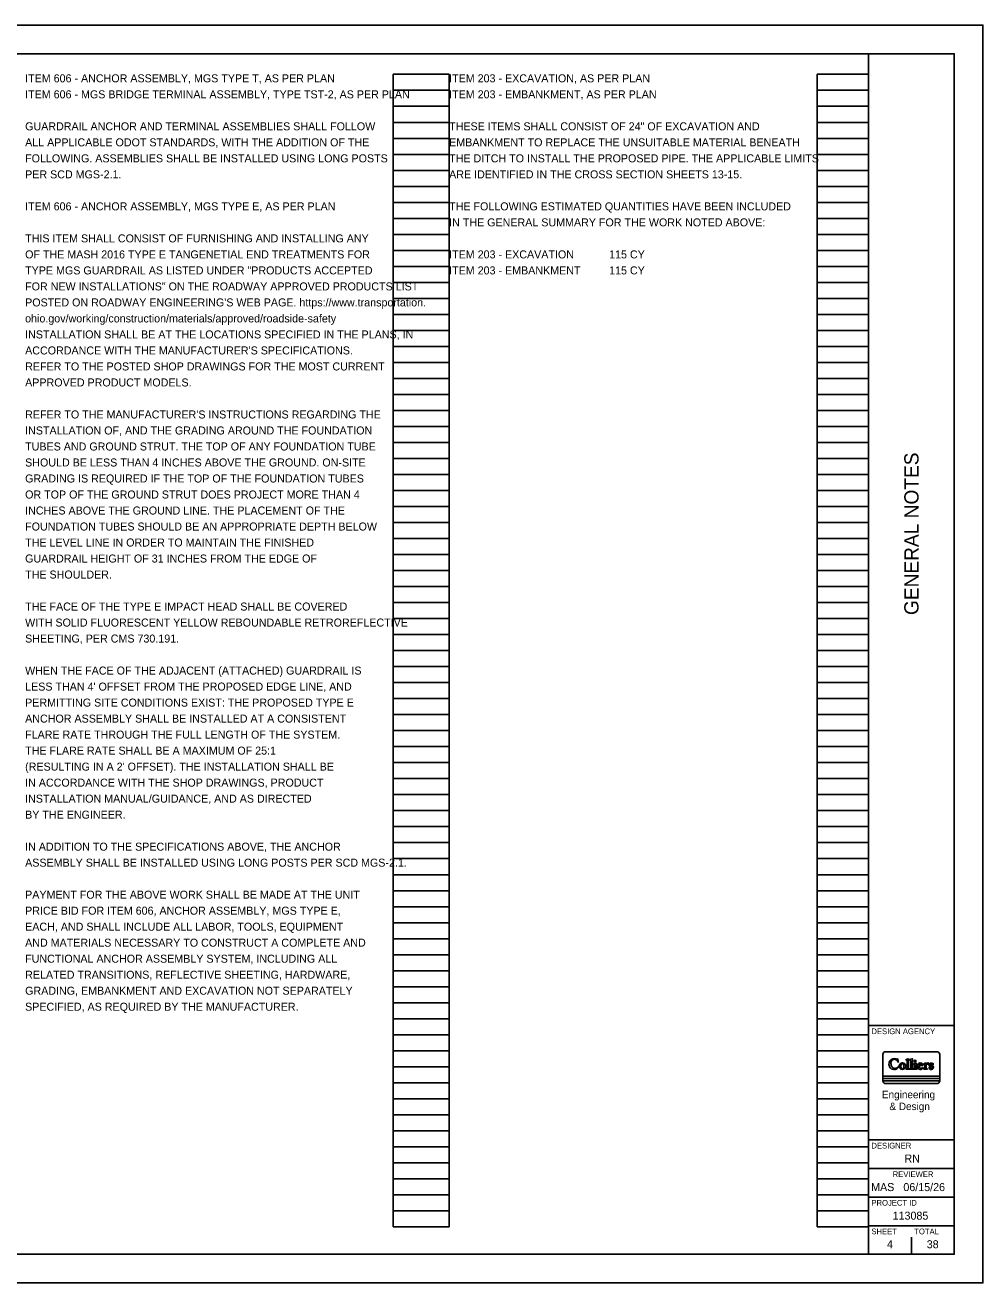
# Model space of a CAD drawing. Extents: x -24.6 to 58.4, y 0 to 22.8.
# Drawn here: x 17.24 to 34, y 0 to 22 of the extents above; entities that cross this region are included whole.
import ezdxf

# ---------------------------------------------------------------- set-up
doc = ezdxf.new("R2010")
doc.units = 0
for name, color, linetype in [('SH_Border', 7, 'Continuous'), ('SH_Cut_Line', 7, 'Continuous'), ('SH_Data', 7, 'Continuous'), ('SH_Text', 7, 'Continuous')]:
    doc.layers.add(name, color=color, linetype=linetype)

msp = doc.modelspace()

# ---------------------------------------------------------------- linework, layer by layer
at = {"layer": 'SH_Border'}
for p, q in [((32, 0.5), (32, 21.5)), ((32, 4.5), (33.5, 4.5)), ((32, 2.5), (33.5, 2.5)), ((32, 2), (33.5, 2)), ((32, 1.5), (33.5, 1.5)), ((32, 1), (33.5, 1))]:
    msp.add_line(p, q, dxfattribs=at)
msp.add_lwpolyline([(1.5, 21.5), (33.5, 21.5), (33.5, 0.5), (1.5, 0.5)], close=True, dxfattribs=at)
at = {"layer": 'SH_Cut_Line'}
msp.add_lwpolyline([(0, 0), (34, 0), (34, 22), (0, 22)], close=True, dxfattribs=at)
at = {"layer": 'SH_Data'}
for p, q in [((23.68, 0.98), (23.68, 21.14)), ((23.68, 21.14), (24.66, 21.14)), ((24.66, 0.98), (24.66, 21.14)), ((31.1, 0.98), (31.1, 21.14)), ((31.1, 21.14), (32, 21.14)), ((32, 0.98), (32, 21.14)), ((23.68, 20.86), (24.66, 20.86)), ((31.1, 20.86), (32, 20.86)), ((23.68, 20.58), (24.66, 20.58)), ((31.1, 20.58), (32, 20.58)), ((23.68, 20.3), (24.66, 20.3)), ((31.1, 20.3), (32, 20.3)), ((23.68, 20.02), (24.66, 20.02)), ((31.1, 20.02), (32, 20.02)), ((23.68, 19.74), (24.66, 19.74)), ((31.1, 19.74), (32, 19.74)), ((23.68, 19.46), (24.66, 19.46)), ((31.1, 19.46), (32, 19.46)), ((23.68, 19.18), (24.66, 19.18)), ((31.1, 19.18), (32, 19.18)), ((23.68, 18.9), (24.66, 18.9)), ((31.1, 18.9), (32, 18.9)), ((23.68, 18.62), (24.66, 18.62)), ((31.1, 18.62), (32, 18.62)), ((23.68, 18.34), (24.66, 18.34)), ((31.1, 18.34), (32, 18.34)), ((23.68, 18.06), (24.66, 18.06)), ((31.1, 18.06), (32, 18.06)), ((23.68, 17.78), (24.66, 17.78)), ((31.1, 17.78), (32, 17.78)), ((23.68, 17.5), (24.66, 17.5)), ((31.1, 17.5), (32, 17.5)), ((23.68, 17.22), (24.66, 17.22)), ((31.1, 17.22), (32, 17.22)), ((23.68, 16.94), (24.66, 16.94)), ((31.1, 16.94), (32, 16.94)), ((23.68, 16.66), (24.66, 16.66)), ((31.1, 16.66), (32, 16.66)), ((23.68, 16.38), (24.66, 16.38)), ((31.1, 16.38), (32, 16.38)), ((23.68, 16.1), (24.66, 16.1)), ((31.1, 16.1), (32, 16.1)), ((23.68, 15.82), (24.66, 15.82)), ((31.1, 15.82), (32, 15.82)), ((23.68, 15.54), (24.66, 15.54)), ((31.1, 15.54), (32, 15.54)), ((23.68, 15.26), (24.66, 15.26)), ((31.1, 15.26), (32, 15.26)), ((23.68, 14.98), (24.66, 14.98)), ((31.1, 14.98), (32, 14.98)), ((23.68, 14.7), (24.66, 14.7)), ((31.1, 14.7), (32, 14.7)), ((23.68, 14.42), (24.66, 14.42)), ((31.1, 14.42), (32, 14.42)), ((23.68, 14.14), (24.66, 14.14)), ((31.1, 14.14), (32, 14.14)), ((23.68, 13.86), (24.66, 13.86)), ((31.1, 13.86), (32, 13.86)), ((23.68, 13.58), (24.66, 13.58)), ((31.1, 13.58), (32, 13.58)), ((23.68, 13.3), (24.66, 13.3)), ((31.1, 13.3), (32, 13.3)), ((23.68, 13.02), (24.66, 13.02)), ((31.1, 13.02), (32, 13.02)), ((23.68, 12.74), (24.66, 12.74)), ((31.1, 12.74), (32, 12.74)), ((23.68, 12.46), (24.66, 12.46)), ((31.1, 12.46), (32, 12.46)), ((23.68, 12.18), (24.66, 12.18)), ((31.1, 12.18), (32, 12.18)), ((23.68, 11.9), (24.66, 11.9)), ((31.1, 11.9), (32, 11.9)), ((23.68, 11.62), (24.66, 11.62)), ((31.1, 11.62), (32, 11.62)), ((23.68, 11.34), (24.66, 11.34)), ((31.1, 11.34), (32, 11.34)), ((23.68, 11.06), (24.66, 11.06)), ((31.1, 11.06), (32, 11.06)), ((23.68, 10.78), (24.66, 10.78)), ((31.1, 10.78), (32, 10.78)), ((23.68, 10.5), (24.66, 10.5)), ((31.1, 10.5), (32, 10.5)), ((23.68, 10.22), (24.66, 10.22)), ((31.1, 10.22), (32, 10.22)), ((23.68, 9.94), (24.66, 9.94)), ((31.1, 9.94), (32, 9.94)), ((23.68, 9.66), (24.66, 9.66)), ((31.1, 9.66), (32, 9.66)), ((23.68, 9.38), (24.66, 9.38)), ((31.1, 9.38), (32, 9.38)), ((23.68, 9.1), (24.66, 9.1)), ((31.1, 9.1), (32, 9.1)), ((23.68, 8.82), (24.66, 8.82)), ((31.1, 8.82), (32, 8.82)), ((23.68, 8.54), (24.66, 8.54)), ((31.1, 8.54), (32, 8.54)), ((23.68, 8.26), (24.66, 8.26)), ((31.1, 8.26), (32, 8.26)), ((23.68, 7.98), (24.66, 7.98)), ((31.1, 7.98), (32, 7.98)), ((23.68, 7.7), (24.66, 7.7)), ((31.1, 7.7), (32, 7.7)), ((23.68, 7.42), (24.66, 7.42)), ((31.1, 7.42), (32, 7.42)), ((23.68, 7.14), (24.66, 7.14)), ((31.1, 7.14), (32, 7.14)), ((23.68, 6.86), (24.66, 6.86)), ((31.1, 6.86), (32, 6.86)), ((23.68, 6.58), (24.66, 6.58)), ((31.1, 6.58), (32, 6.58)), ((23.68, 6.3), (24.66, 6.3)), ((31.1, 6.3), (32, 6.3)), ((23.68, 6.02), (24.66, 6.02)), ((31.1, 6.02), (32, 6.02)), ((23.68, 5.74), (24.66, 5.74)), ((31.1, 5.74), (32, 5.74)), ((23.68, 5.46), (24.66, 5.46)), ((31.1, 5.46), (32, 5.46)), ((23.68, 5.18), (24.66, 5.18)), ((31.1, 5.18), (32, 5.18)), ((23.68, 4.9), (24.66, 4.9)), ((31.1, 4.9), (32, 4.9)), ((23.68, 4.62), (24.66, 4.62)), ((31.1, 4.62), (32, 4.62)), ((23.68, 4.34), (24.66, 4.34)), ((31.1, 4.34), (32, 4.34)), ((23.68, 4.06), (24.66, 4.06)), ((31.1, 4.06), (32, 4.06)), ((33.195, 4.043), (32.299, 4.043)), ((23.68, 3.78), (24.66, 3.78)), ((31.1, 3.78), (32, 3.78)), ((32.506, 3.913), (32.507, 3.91)), ((32.511, 3.864), (32.513, 3.859)), ((32.518, 3.765), (32.522, 3.77)), ((32.596, 3.846), (32.59, 3.846)), ((32.667, 3.745), (32.658, 3.745)), ((32.674, 3.881), (32.674, 3.753)), ((32.701, 3.752), (32.701, 3.916)), ((32.734, 3.745), (32.707, 3.745)), ((32.741, 3.879), (32.741, 3.751)), ((32.768, 3.751), (32.768, 3.916)), ((32.799, 3.745), (32.774, 3.745)), ((32.827, 3.846), (32.791, 3.832)), ((32.805, 3.812), (32.805, 3.751)), ((32.832, 3.749), (32.832, 3.843)), ((32.845, 3.745), (32.836, 3.745)), ((32.886, 3.802), (32.947, 3.802)), ((32.919, 3.81), (32.887, 3.81)), ((32.975, 3.745), (32.968, 3.745)), ((33, 3.846), (32.969, 3.831)), ((32.969, 3.825), (32.976, 3.821)), ((32.982, 3.81), (32.982, 3.753)), ((33.007, 3.828), (33.006, 3.843)), ((33.01, 3.753), (33.01, 3.807)), ((33.026, 3.745), (33.017, 3.745)), ((33.11, 3.833), (33.125, 3.816)), ((33.132, 3.82), (33.13, 3.835)), ((32.249, 3.533), (33.244, 3.533)), ((33.244, 3.533), (32.249, 3.533)), ((32.658, 3.737), (32.845, 3.737)), ((32.968, 3.737), (33.026, 3.737)), ((33.245, 3.535), (33.245, 3.575)), ((23.68, 3.5), (24.66, 3.5)), ((31.1, 3.5), (32, 3.5)), ((32.299, 3.485), (33.195, 3.485)), ((32.75, 3.5), (32.75, 3.5)), ((23.68, 3.22), (24.66, 3.22)), ((31.1, 3.22), (32, 3.22)), ((23.68, 2.94), (24.66, 2.94)), ((31.1, 2.94), (32, 2.94)), ((23.68, 2.66), (24.66, 2.66)), ((31.1, 2.66), (32, 2.66)), ((23.68, 2.38), (24.66, 2.38)), ((31.1, 2.38), (32, 2.38)), ((23.68, 2.1), (24.66, 2.1)), ((31.1, 2.1), (32, 2.1)), ((23.68, 1.82), (24.66, 1.82)), ((31.1, 1.82), (32, 1.82)), ((23.68, 1.54), (24.66, 1.54)), ((31.1, 1.54), (32, 1.54)), ((23.68, 1.26), (24.66, 1.26)), ((31.1, 1.26), (32, 1.26)), ((23.68, 0.98), (24.66, 0.98)), ((31.1, 0.98), (32, 0.98)), ((32.375, 0.675), (32.375, 0.675)), ((32.75, 0.5), (32.75, 0.8))]:
    msp.add_line(p, q, dxfattribs=at)
for points in [[(32.249, 3.993), (32.249, 3.617), (33.245, 3.617), (33.245, 3.993)], [(32.521, 3.861), (32.516, 3.886), (32.514, 3.914)], [(33.245, 3.575), (32.249, 3.575), (32.249, 3.535)]]:
    msp.add_lwpolyline(points, dxfattribs=at)
msp.add_lwpolyline([(33.245, 3.617), (32.249, 3.617), (32.249, 3.575), (33.245, 3.575)], close=True, dxfattribs=at)
msp.add_circle((32.815, 3.879), 0.0155, dxfattribs=at)
for centre, radius, start, end in [((32.299, 3.993), 0.0498, 90, 180), ((33.195, 3.993), 0.0498, 0, 90), ((32.456, 3.826), 0.0996, 122.7772, 219.4331), ((32.445, 3.817), 0.0857, 219.4331, 285.3506), ((32.526, 3.843), 0.135, 175.9543, 206.5569), ((32.457, 3.848), 0.0652, 110.6135, 175.9543), ((32.45, 3.835), 0.0884, 54.7696, 122.7772), ((32.458, 3.81), 0.059, 206.5569, 271.2175), ((32.45, 3.867), 0.0454, 67.8997, 110.6135), ((32.458, 3.828), 0.0773, 271.2175, 317.7042), ((32.437, 3.835), 0.0794, 21.2674, 67.8997), ((32.44, 3.834), 0.104, 285.3506, 318.3029), ((32.503, 3.91), 0.00381, 234.7696, 0.2433), ((32.51, 3.914), 0.00392, 10.93, 183.8175), ((32.516, 3.862), 0.00427, 213.048, 354.7379), ((32.518, 3.773), 0.00456, 317.5815, 137.7042), ((32.594, 3.79), 0.0573, 155.0154, 195.9836), ((32.593, 3.79), 0.0568, 195.9836, 247.4134), ((32.591, 3.791), 0.0549, 91.4708, 155.0154), ((32.627, 3.79), 0.0628, 159.8672, 197.1421), ((32.617, 3.787), 0.0527, 197.1421, 229.9048), ((32.613, 3.795), 0.0485, 128.4847, 159.8672), ((32.592, 3.822), 0.0143, 51.5153, 128.4847), ((32.593, 3.759), 0.0157, 229.9048, 310.0952), ((32.596, 3.791), 0.0547, 22.5432, 90), ((32.572, 3.797), 0.0457, 8.6045, 51.5153), ((32.573, 3.782), 0.0463, 311.5123, 356.3189), ((32.586, 3.797), 0.0652, 292.5866, 340.2533), ((32.532, 3.787), 0.0872, 354.2931, 11.1311), ((32.599, 3.792), 0.0508, 340.2533, 22.5432), ((32.657, 3.901), 0.00323, 122.5943, 271.3615), ((32.658, 3.741), 0.00412, 90, 270), ((32.544, 4.221), 0.336, 289.2258, 296.5694), ((32.657, 3.881), 0.0166, 0, 91.3615), ((32.667, 3.752), 0.00695, 270, 7.6881), ((32.696, 3.916), 0.00466, 0.7043, 112.8976), ((32.709, 3.752), 0.00806, 180, 256.9766), ((32.724, 3.902), 0.00377, 108.5217, 257.147), ((32.641, 4.168), 0.275, 287.2899, 295.7863), ((32.722, 3.879), 0.019, 0, 85.065), ((32.734, 3.751), 0.0065, 270, 3.1556), ((32.763, 3.916), 0.00504, 3.9002, 114.2106), ((32.775, 3.751), 0.00652, 179.2506, 264.6402), ((32.794, 3.829), 0.00399, 126.9098, 263.7558), ((32.792, 3.812), 0.0128, 0, 83.7558), ((32.799, 3.75), 0.00532, 270, 12.3402), ((32.829, 3.843), 0.00324, 356.2318, 111.3032), ((32.837, 3.749), 0.00485, 180, 266.7746), ((32.845, 3.741), 0.00381, 270, 90), ((32.936, 3.789), 0.0786, 158.9201, 196.7689), ((32.904, 3.78), 0.0455, 196.7689, 259.4625), ((32.906, 3.801), 0.0468, 107.3884, 158.9201), ((32.928, 3.794), 0.0459, 174.8749, 230.9242), ((32.886, 3.798), 0.00367, 90, 174.8749), ((32.917, 3.807), 0.0332, 120.4846, 167.2691), ((32.887, 3.813), 0.00338, 167.2691, 270), ((32.909, 3.792), 0.0557, 72.6116, 107.3884), ((32.906, 3.79), 0.0563, 259.4625, 329.9587), ((32.92, 3.784), 0.0321, 230.9242, 328.1623), ((32.907, 3.823), 0.0144, 42.3189, 120.4846), ((32.901, 3.817), 0.0231, 354.1231, 42.3189), ((32.918, 3.815), 0.00543, 277.2594, 354.1231), ((32.914, 3.809), 0.0381, 357.2625, 72.6116), ((32.946, 3.807), 0.00555, 272.7564, 357.2625), ((32.951, 3.764), 0.00454, 329.9587, 148.1623), ((32.968, 3.741), 0.00381, 91.0116, 270), ((32.971, 3.828), 0.0034, 121.2415, 241.2505), ((32.975, 3.752), 0.00704, 270, 9.7141), ((32.969, 3.81), 0.0136, 0, 59.7444), ((33.002, 3.843), 0.00375, 6.4513, 116.174), ((33.009, 3.828), 0.00158, 185.3907, 323.4477), ((33.094, 3.765), 0.104, 130.2856, 143.4477), ((33.033, 3.807), 0.0235, 141.4263, 180.0327), ((33.018, 3.752), 0.00796, 179.3196, 263.9925), ((33.023, 3.815), 0.0105, 58.8554, 141.4263), ((33.038, 3.831), 0.0179, 49.7144, 130.2856), ((33.026, 3.741), 0.00381, 270, 90), ((33.038, 3.839), 0.018, 238.8554, 310.2856), ((33.041, 3.835), 0.0124, 310.2856, 49.7144), ((33.093, 3.812), 0.0332, 143.4089, 199.3264), ((33.065, 3.768), 0.00485, 20.4198, 193.2731), ((32.948, 3.74), 0.116, 4.8826, 13.2731), ((33.087, 3.81), 0.0263, 199.3264, 242.7351), ((33.077, 3.751), 0.014, 184.8826, 242.2064), ((33.093, 3.812), 0.0334, 105.6066, 143.4089), ((33.118, 3.787), 0.0516, 200.4198, 231.7135), ((33.093, 3.782), 0.0486, 242.2064, 319.0024), ((33.141, 3.915), 0.144, 242.7351, 255.1442), ((33.093, 3.822), 0.0133, 123.6114, 236.3886), ((33.099, 3.79), 0.0558, 61.5074, 105.6066), ((33.099, 3.813), 0.0238, 78.1441, 123.6114), ((33.111, 3.85), 0.0468, 236.3886, 262.0524), ((33.098, 3.761), 0.0185, 231.7135, 325.4966), ((33.101, 3.825), 0.0115, 42.5173, 78.1441), ((33.1, 3.76), 0.016, 325.4966, 75.1442), ((33.099, 3.763), 0.0407, 40.9976, 82.0524), ((33.128, 3.819), 0.00433, 219.7222, 9.1323), ((33.122, 3.833), 0.00795, 16.8946, 61.5074), ((33.107, 3.77), 0.0305, 319.0024, 40.9976), ((32.299, 3.535), 0.0498, 180, 183.1495), ((32.299, 3.535), 0.0498, 183.1495, 270), ((32.591, 3.784), 0.0512, 247.4134, 292.5866), ((33.195, 3.535), 0.0498, 270, 356.8505), ((33.195, 3.535), 0.0498, 356.8505, 0)]:
    msp.add_arc(centre, radius, start, end, dxfattribs=at)

# ---------------------------------------------------------------- texts
msp.add_text('GENERAL NOTES', height=0.25, rotation=90, dxfattribs=at).set_placement((32.875, 11.682))
for s, height, p in [('DESIGN AGENCY', 0.1, (32.05, 4.35)), ('Engineering', 0.13025, (32.234, 3.229)), ('& Design', 0.1303, (32.365, 3.022)), ('DESIGNER', 0.1, (32.05, 2.35)), ('RN', 0.14, (32.628, 2.105)), ('REVIEWER', 0.1, (32.422, 1.85)), ('MAS', 0.14, (32.045, 1.605)), ('06/15/26', 0.14, (32.609, 1.605)), ('PROJECT ID', 0.1, (32.05, 1.35)), ('113085', 0.14, (32.421, 1.105)), ('SHEET', 0.1, (32.05, 0.85)), ('TOTAL', 0.1, (32.8, 0.85)), ('4', 0.14, (32.322, 0.605)), ('38', 0.14, (33.018, 0.605))]:
    msp.add_text(s, height=height, dxfattribs=at).set_placement(p)
at = {"layer": 'SH_Text'}
for s, p in [('ITEM 606 - ANCHOR ASSEMBLY, MGS TYPE T, AS PER PLAN', (17.24, 21)), ('ITEM 203 - EXCAVATION, AS PER PLAN', (24.66, 21)), ('ITEM 606 - MGS BRIDGE TERMINAL ASSEMBLY, TYPE TST-2, AS PER PLAN', (17.24, 20.72)), ('ITEM 203 - EMBANKMENT, AS PER PLAN', (24.66, 20.72)), ('GUARDRAIL ANCHOR AND TERMINAL ASSEMBLIES SHALL FOLLOW', (17.24, 20.16)), ('THESE ITEMS SHALL CONSIST OF 24" OF EXCAVATION AND', (24.66, 20.16)), ('ALL APPLICABLE ODOT STANDARDS, WITH THE ADDITION OF THE', (17.24, 19.88)), ('EMBANKMENT TO REPLACE THE UNSUITABLE MATERIAL BENEATH', (24.66, 19.88)), ('FOLLOWING. ASSEMBLIES SHALL BE INSTALLED USING LONG POSTS', (17.24, 19.6)), ('THE DITCH TO INSTALL THE PROPOSED PIPE. THE APPLICABLE LIMITS', (24.66, 19.6)), ('PER SCD MGS-2.1.', (17.24, 19.32)), ('ARE IDENTIFIED IN THE CROSS SECTION SHEETS 13-15.', (24.66, 19.32)), ('ITEM 606 - ANCHOR ASSEMBLY, MGS TYPE E, AS PER PLAN', (17.24, 18.76)), ('THE FOLLOWING ESTIMATED QUANTITIES HAVE BEEN INCLUDED', (24.66, 18.76)), ('IN THE GENERAL SUMMARY FOR THE WORK NOTED ABOVE:', (24.66, 18.48)), ('THIS ITEM SHALL CONSIST OF FURNISHING AND INSTALLING ANY', (17.24, 18.2)), ('OF THE MASH 2016 TYPE E TANGENETIAL END TREATMENTS FOR', (17.24, 17.92)), ('ITEM 203 - EXCAVATION', (24.66, 17.92)), ('115 CY', (27.46, 17.92)), ('TYPE MGS GUARDRAIL AS LISTED UNDER "PRODUCTS ACCEPTED', (17.24, 17.64)), ('ITEM 203 - EMBANKMENT', (24.66, 17.64)), ('115 CY', (27.46, 17.64)), ('FOR NEW INSTALLATIONS" ON THE ROADWAY APPROVED PRODUCTS LIST ', (17.24, 17.36)), ("POSTED ON ROADWAY ENGINEERING'S WEB PAGE. https://www.transportation.", (17.24, 17.08)), ('ohio.gov/working/construction/materials/approved/roadside-safety', (17.24, 16.8)), ('INSTALLATION SHALL BE AT THE LOCATIONS SPECIFIED IN THE PLANS, IN', (17.24, 16.52)), ("ACCORDANCE WITH THE MANUFACTURER'S SPECIFICATIONS.", (17.24, 16.24)), ('REFER TO THE POSTED SHOP DRAWINGS FOR THE MOST CURRENT', (17.24, 15.96)), ('APPROVED PRODUCT MODELS.', (17.24, 15.68)), ("REFER TO THE MANUFACTURER'S INSTRUCTIONS REGARDING THE", (17.24, 15.12)), ('INSTALLATION OF, AND THE GRADING AROUND THE FOUNDATION', (17.24, 14.84)), ('TUBES AND GROUND STRUT. THE TOP OF ANY FOUNDATION TUBE', (17.24, 14.56)), ('SHOULD BE LESS THAN 4 INCHES ABOVE THE GROUND. ON-SITE', (17.24, 14.28)), ('GRADING IS REQUIRED IF THE TOP OF THE FOUNDATION TUBES', (17.24, 14)), ('OR TOP OF THE GROUND STRUT DOES PROJECT MORE THAN 4', (17.24, 13.72)), ('INCHES ABOVE THE GROUND LINE. THE PLACEMENT OF THE', (17.24, 13.44)), ('FOUNDATION TUBES SHOULD BE AN APPROPRIATE DEPTH BELOW', (17.24, 13.16)), ('THE LEVEL LINE IN ORDER TO MAINTAIN THE FINISHED', (17.24, 12.88)), ('GUARDRAIL HEIGHT OF 31 INCHES FROM THE EDGE OF', (17.24, 12.6)), ('THE SHOULDER.', (17.24, 12.32)), ('THE FACE OF THE TYPE E IMPACT HEAD SHALL BE COVERED', (17.24, 11.76)), ('WITH SOLID FLUORESCENT YELLOW REBOUNDABLE RETROREFLECTIVE', (17.24, 11.48)), ('SHEETING, PER CMS 730.191.', (17.24, 11.2)), ('WHEN THE FACE OF THE ADJACENT (ATTACHED) GUARDRAIL IS', (17.24, 10.64)), ("LESS THAN 4' OFFSET FROM THE PROPOSED EDGE LINE, AND", (17.24, 10.36)), ('PERMITTING SITE CONDITIONS EXIST: THE PROPOSED TYPE E', (17.24, 10.08)), ('ANCHOR ASSEMBLY SHALL BE INSTALLED AT A CONSISTENT', (17.24, 9.8)), ('FLARE RATE THROUGH THE FULL LENGTH OF THE SYSTEM.', (17.24, 9.52)), ('THE FLARE RATE SHALL BE A MAXIMUM OF 25:1', (17.24, 9.24)), ("(RESULTING IN A 2' OFFSET). THE INSTALLATION SHALL BE", (17.24, 8.96)), ('IN ACCORDANCE WITH THE SHOP DRAWINGS, PRODUCT', (17.24, 8.68)), ('INSTALLATION MANUAL/GUIDANCE, AND AS DIRECTED', (17.24, 8.4)), ('BY THE ENGINEER.', (17.24, 8.12)), ('IN ADDITION TO THE SPECIFICATIONS ABOVE, THE ANCHOR', (17.24, 7.56)), ('ASSEMBLY SHALL BE INSTALLED USING LONG POSTS PER SCD MGS-2.1.', (17.24, 7.28)), ('PAYMENT FOR THE ABOVE WORK SHALL BE MADE AT THE UNIT', (17.24, 6.72)), ('PRICE BID FOR ITEM 606, ANCHOR ASSEMBLY, MGS TYPE E,', (17.24, 6.44)), ('EACH, AND SHALL INCLUDE ALL LABOR, TOOLS, EQUIPMENT', (17.24, 6.16)), ('AND MATERIALS NECESSARY TO CONSTRUCT A COMPLETE AND', (17.24, 5.88)), ('FUNCTIONAL ANCHOR ASSEMBLY SYSTEM, INCLUDING ALL', (17.24, 5.6)), ('RELATED TRANSITIONS, REFLECTIVE SHEETING, HARDWARE,', (17.24, 5.32)), ('GRADING, EMBANKMENT AND EXCAVATION NOT SEPARATELY', (17.24, 5.04)), ('SPECIFIED, AS REQUIRED BY THE MANUFACTURER.', (17.24, 4.76))]:
    msp.add_text(s, height=0.14, dxfattribs=at).set_placement(p)

doc.saveas('drawing.dxf')
